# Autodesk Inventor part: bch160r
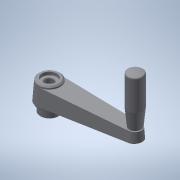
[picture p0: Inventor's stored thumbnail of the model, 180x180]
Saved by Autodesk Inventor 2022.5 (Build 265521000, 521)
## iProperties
Created: 2016-12
Part Number: bch160r
Material: 一般
Document SubType Name: Modeling
Designer: imaocorp
Density: 1 g/cm^3
Appearance: 既定
Author: imaocorp
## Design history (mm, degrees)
node "bch160r.x_t1"
node "bch160r"
node "Base1"
